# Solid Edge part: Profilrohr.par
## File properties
Username: bmolnar
Dokumentum tartalom típus: 0
Author: bmolnar
Last saved by: bmolnar
Revision: 84
Sűrűség: 0,000 kg/m^3
Pontosság: 0,990
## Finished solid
Body 1: solid body, 115 faces, 338 edges, 224 vertices.
  Faces by surface: cylinder 59, plane 56
  Edges by curve: line 220, circle 118
Bounding box of the edges (mm): 95.500 x 95.500 x 84.000, from (-47.75, -47.75, -55) to (47.75, 47.75, 29).
Cylindrical faces by radius (mm): R0.2 x24, R0.5 x24, R1 x4, R10 x4, R13.5 x2, R40 x1
Planar faces by outward normal: +x 13, +y 14, +z 1, -x 13, -y 14, -z 1
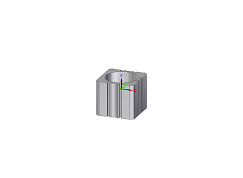
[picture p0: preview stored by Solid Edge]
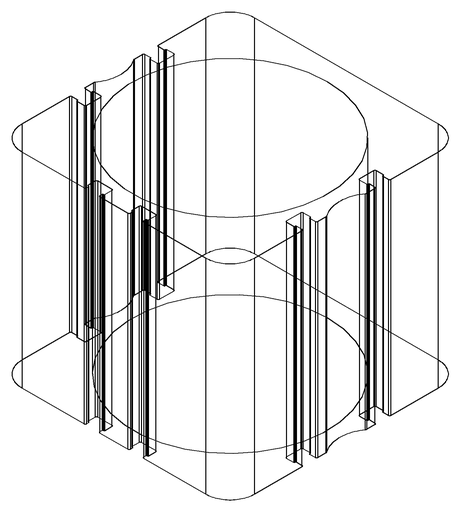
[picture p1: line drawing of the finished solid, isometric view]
